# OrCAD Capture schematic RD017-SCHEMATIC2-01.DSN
size A3
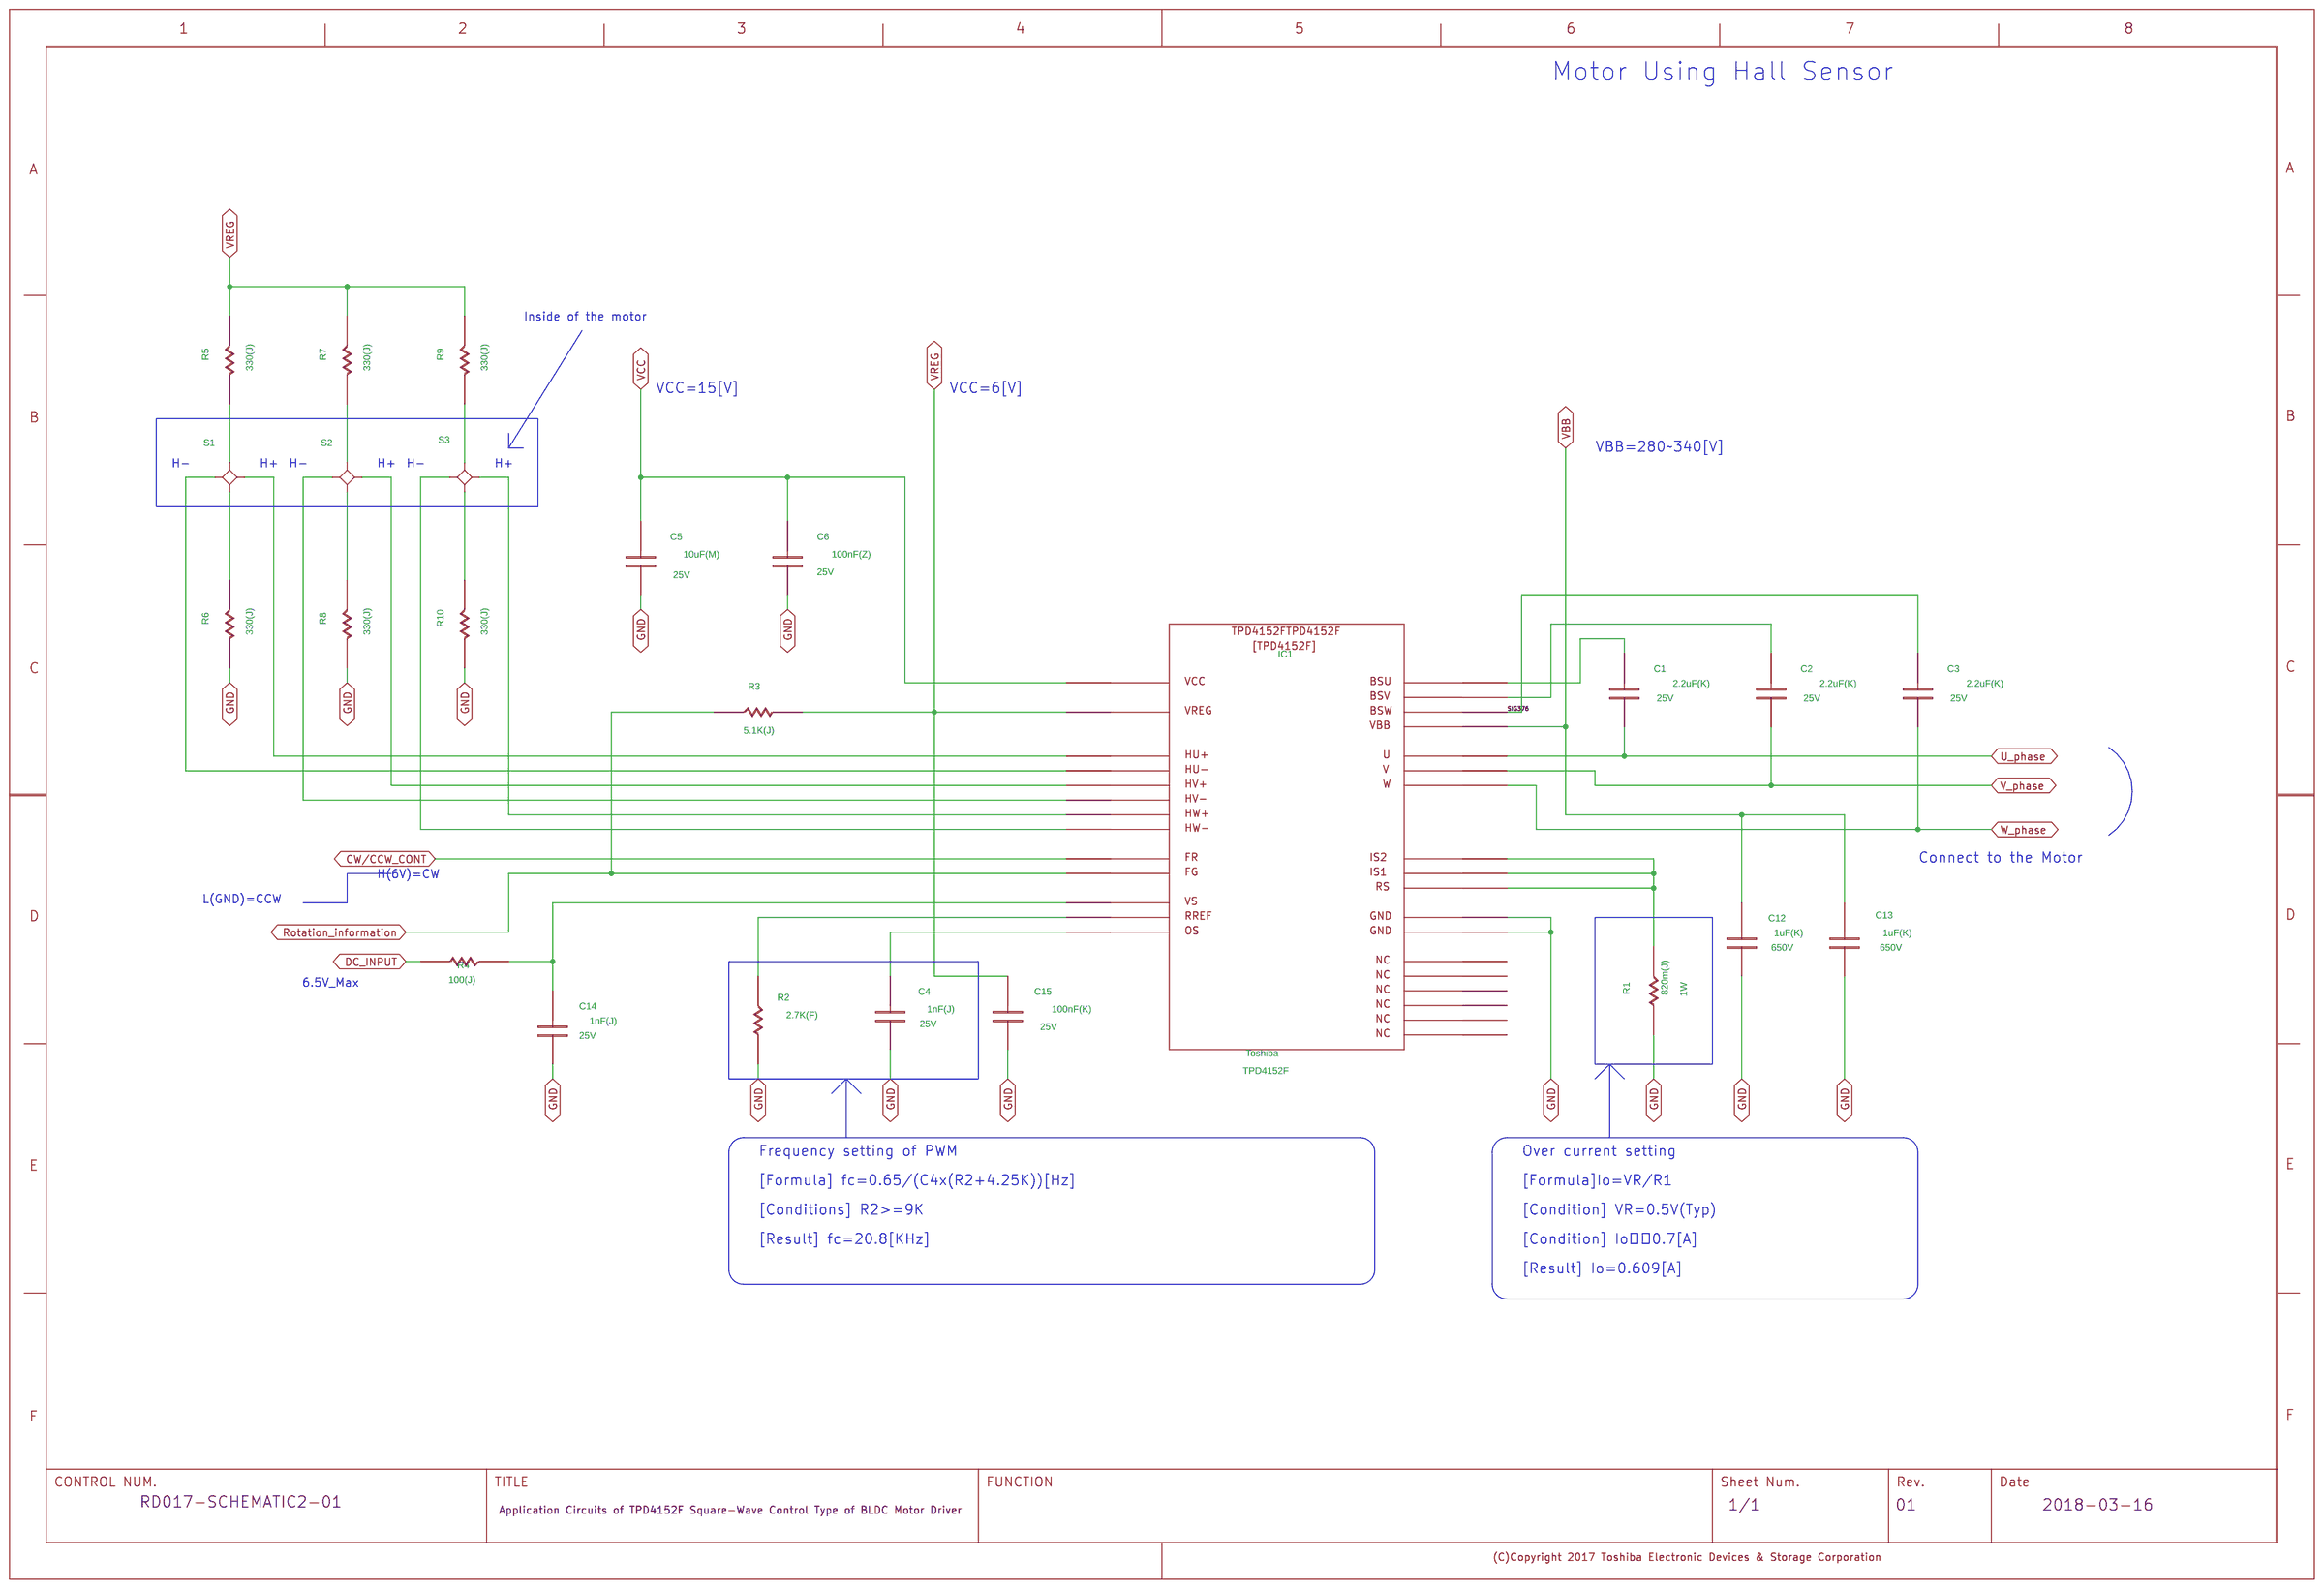
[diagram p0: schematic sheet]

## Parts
C1  C
C2  C
C3  C
C4  C
C5  C
C6  C
C12  C
C13  C
C14  C
C15  C
IC1  S-TPD4152F
R1  R
R2  R
R3  R
R4  R
R5  R
R6  R
R7  R
R8  R
R9  R
R10  R
S1  STAR4
S2  STAR4
S3  STAR4
U?#1  WAKU_DEF100

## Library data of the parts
C1-C3 = C: COMPONENTTYPE: 4; GCOUNT: 1; MAXGCOUNT: 1; SIZECODESMD: 2012; VAL1: 2.2uF(K); VAL2: 25V
C4 C14 = C: COMPONENTTYPE: 4; GCOUNT: 1; MAXGCOUNT: 1; SIZECODESMD: 1608; VAL1: 1nF(J); VAL2: 25V
C5 = C: COMPONENTTYPE: 4; GCOUNT: 1; MAXGCOUNT: 1; SIZECODESMD: 1608; VAL1: 10uF(M); VAL2: 25V
C6 = C: COMPONENTTYPE: 4; GCOUNT: 1; MAXGCOUNT: 1; SIZECODESMD: 1608; VAL1: 100nF(Z); VAL2: 25V
C12 C13 = C: COMPONENTTYPE: 4; GCOUNT: 1; MAXGCOUNT: 1; SIZECODESMD: DIP; VAL1: 1uF(K); VAL2: 650V; VAL3: ECQE6105KF
C15 = C: COMPONENTTYPE: 4; GCOUNT: 1; MAXGCOUNT: 1; SIZECODESMD: 1608; VAL1: 100nF(K); VAL2: 25V
IC1 = S-TPD4152F: COMPONENTTYPE: 4; USERCOMPTEXT1: Toshiba; VAL1: TPD4152F
R1 = R: COMPONENTTYPE: 4; GCOUNT: 1; MAXGCOUNT: 1; VAL1: 820m(J); VAL2: 1W; VAL3: SL1TTER85F
R2 = R: COMPONENTTYPE: 4; GCOUNT: 1; MAXGCOUNT: 1; SIZECODESMD: 1608; VAL1: 2.7K(F); VAL2: 100mW
R3 = R: COMPONENTTYPE: 4; GCOUNT: 1; MAXGCOUNT: 1; SIZECODESMD: 1608; VAL1: 5.1K(J); VAL2: 100mW
R4 = R: COMPONENTTYPE: 4; GCOUNT: 1; MAXGCOUNT: 1; SIZECODESMD: 1608; VAL1: 100(J); VAL2: 100mW
R5-R10 = R: COMPONENTTYPE: 4; GCOUNT: 1; MAXGCOUNT: 1; SIZECODESMD: 1608; VAL1: 330(J); VAL2: 100mW
S1-S3 = STAR4: COMPONENTTYPE: 4; SIZECODESMD: 4SOP; VAL1: HW-101A; VAL3: HW-101A
U?#1 = WAKU_DEF100: COMPONENTTYPE: 2; DATE: 2018-03-16; DRAWINGNUMBER: RD017-SCHEMATIC2-01; REVISION: 01; SHEETNUMBER: 1/1; TITLE: Application Circuits of TPD4152F Square-Wave Control Type of BLDC Motor Driver; UPDATEDATE: 2018/03/16; UPDATETIME: 17:55:58; UPDATEUSER: g4302510

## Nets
GND: C4.1 C5.1 C6.1 C12.1 C13.1 C14.1 C15.1 IC1.11 IC1.31 R1.1 R2.1 R6.1 R8.1 R10.1
VCC: C5.2 C6.2 IC1.18
CW/CCW_CONT: IC1.22
DC_INPUT: R4.1
Rotation_information: IC1.20 R3.2
SIG376: C3.2 IC1.3
U_phase: C1.1 IC1.9
V_phase: C2.1 IC1.6
VBB: C12.2 C13.2 IC1.4
VREG: C15.2 IC1.19 R3.1 R5.2 R7.2 R9.2
W_phase: C3.1 IC1.2
N00489: C1.2 IC1.10
N00499: C2.2 IC1.5
N00519: IC1.1 IC1.7 IC1.14 R1.2
N00561: IC1.16 R2.2
N00567: C4.2 IC1.17
N00585: C14.2 IC1.15 R4.2
N00653: IC1.29 S1.2
N00661: IC1.28 S1.1
N00669: IC1.26 S2.1
N00677: IC1.24 S3.2
N00685: IC1.23 S3.1
N00693: IC1.27 S2.2
N00741: R5.1 S1.4
N00745: R8.2 S2.3
N00753: R10.2 S3.3
N00757: R6.2 S1.3
N00765: R7.1 S2.4
N00769: R9.1 S3.4

Not connected (* = marked no-connect by the designer): IC1 8 12 13 21 25 30

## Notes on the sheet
- Motor Using Hall Sensor
- Inside of the motor
- VCC=15[V]
- VCC=6[V]
- VBB=280~340[V]
- H-
- H+
- H-
- H+
- H-
- H+
- Connect to the Motor
- H(6V)=CW
- L(GND)=CCW
- 6.5V_Max
- Frequency setting of PWM
- Over current setting
- [Formula] fc=0.65/(C4x(R2+4.25K))[Hz]
- [Formula]Io=VR/R1
- [Conditions] R2>=9K
- [Condition] VR=0.5V(Typ)
- [Result] fc=20.8[KHz]
- [Condition] Io0.7[A]
- [Result] Io=0.609[A]
